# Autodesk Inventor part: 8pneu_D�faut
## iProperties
Created: 2011-01
Part Number: 8pneu_D�faut
Document SubType Name: Modeling
Designer: eric
Density: 1 g/cm^3
Mass: 179.885 g
Surface Area: 527.045 cm^2
Volume: 179.885 cm^3
Author: eric
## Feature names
1. Base1
